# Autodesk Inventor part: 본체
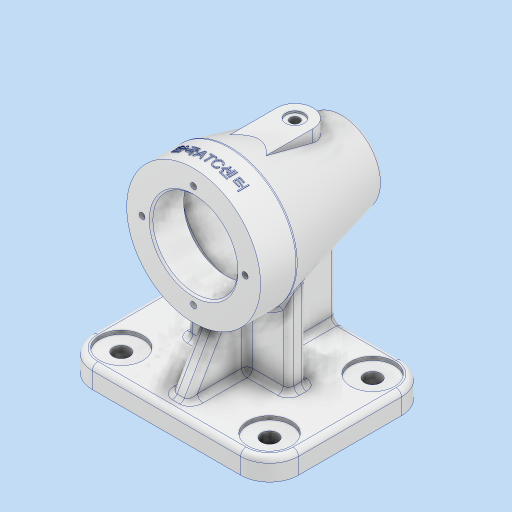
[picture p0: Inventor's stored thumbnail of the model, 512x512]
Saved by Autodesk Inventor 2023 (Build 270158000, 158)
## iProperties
Created: 2024-12
Part Number: 본체
Material: 알루미늄 6061
Document SubType Name: Modeling
Designer: asung
Density: 2.7 g/cm^3
Appearance: 알루미늄 - 평지
Mass: 746.172 g
Surface Area: 670.78 cm^2
Volume: 276.36 cm^3
Author: asung
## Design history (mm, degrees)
sketch "스케치1"
  geometry: L1 (-41, 44.5)-(41, 44.5); L2 (57, 28.5)-(57, -28.5); L3 (41, -44.5)-(-41, -44.5); L4 (-57, -28.5)-(-57, 28.5); L5 (-57, 44.5)-(57, -44.5); L6 (57, 44.5)-(-57, -44.5); C1 r 4.5 at (41, -28.5); C2 r 4.5 at (-41, -28.5); C3 r 4.5 at (-41, 28.5); C4 r 4.5 at (41, 28.5); A1 r 16 centre (41, -28.5) between (41, -44.5) and (57, -28.5); A2 r 16 centre (-41, -28.5) between (-57, -28.5) and (-41, -44.5); A3 r 16 centre (41, 28.5) between (57, 28.5) and (41, 44.5); A4 r 16 centre (-41, 28.5) between (-41, 44.5) and (-57, 28.5); 2 further points
  constraints: 12 end point, 8 centre point, 8 point on circle, 8 point on line, 8 tangent, 4 coincident, 3 equal radius, 3 midpoint, 2 parallel, 1 horizontal, 1 perpendicular
  dimensions: "d0" = 114 distance of L5.end L6.end; "d1" = 89 distance from line of point (0, 44.5) L3; "d2" = 16 radius of A1; "d3" = 4.5 radius of C1; "d4" = 4.5 radius of C2; "d6" = 4.5 radius of C3; "d7" = 4.5 radius of C4
extrude "돌출1" new body sketch "스케치1" distance "d8" = 12; taper "d9" = 0 deg
sketch "스케치2"
  geometry: A1 r 16 centre (-41, 28.5) between (-41, 44.5) and (-57, 28.5) reference; A2 r 16 centre (41, 28.5) between (57, 28.5) and (41, 44.5) reference; A3 r 16 centre (-41, -28.5) between (-57, -28.5) and (-41, -44.5) reference; A4 r 16 centre (41, -28.5) between (41, -44.5) and (57, -28.5) reference; 5 further points
  constraints: 4 coincident
hole "구멍1" sketch "스케치2" at (-41, 28.5), (41, 28.5), (-41, -28.5), (41, -28.5) diameter "d10" = 9; stored, may be unused: countersink angle "d14" = 90 deg, drill point angle "d16" = 0 deg; dims "d11" = 6, "d12" = 24, "d13" = 2, "d15" = 12
sketch "스케치3"
  geometry: L1 (12, -44.5)-(0, -44.5) reference; L2 (0, -44.5)-(0, 44.5) reference; L3 (0, 44.5)-(12, 44.5) reference; L4 (12, 44.5)-(12, -44.5) reference; L5 (82, -85.109)-(82, 114.888); L6 (119, 29.5)-(119, 9.5); L7 (119, 9.5)-(103, -54.5); L8 (103, -54.5)-(82, -54.5); L9 (82, -46.5)-(94.5, -46.5); L10 (97.5, -43.5)-(97.5, -43.5); L11 (97.5, -43.5)-(99.5, -43.5); L12 (103.664, -31.228)-(112.793, 5.287); L13 (107.942, 11.5)-(105.5, 11.5); L14 (105.5, 11.5)-(105.5, 29.5); L15 (105.5, 29.5)-(119, 29.5); L16 (99.5, -43.5)-(99.5, -33.5); L17 (99.5, -33.5)-(100.754, -33.5); A1 r 5 centre (107.942, 6.5) between (112.793, 5.287) and (107.942, 11.5); A2 r 3 centre (94.5, -43.5) between (94.5, -46.5) and (97.5, -43.5); A3 r 3 centre (100.754, -30.5) between (100.754, -33.5) and (103.664, -31.228); 4 further points
  constraints: 26 end point, 6 point on circle, 6 tangent, 4 vertical, 3 centre point, 3 perpendicular, 3 point on line, 2 horizontal, 2 parallel
  dimensions: "d17" = 82 distance between parallel lines of L5 L2; "d18" = 84 vertical distance of L6.start L8.end; "d19" = 15 vertical distance of L3.end L6.start; "d22" = 74 diameter of L6 L5; "d23" = 20 distance of L6.start L6.end; "d25" = 42 diameter of L7.end L5; "d26" = 18 distance of L13.end L14.end; "d27" = 5 distance between parallel lines of L7 L12; "d28" = 47 diameter of L14 L5; "d29" = 5 radius of A1; "d32" = 45 vertical distance of L13.end point (103.096, -33.5); "d33" = 3 distance between parallel lines of L11 L9; "d34" = 35 diameter of L16 L5; "d35" = 31 diameter of L10 L5; "d36" = 3 radius of A2; "d37" = 10 distance of L11.end L16.end; "d38" = 13 distance from line of L9 point (103.096, -33.5); "d39" = 3 radius of A3
revolve "회전1" sketch "스케치3" stored, may be unused: angle "d40" = 90 deg
node "작업 평면1"
sketch "스케치4"
  geometry: L1 (10, -26.5)-(-10, -26.5); L2 (-10, -26.5)-(-10, -0.572); L3 (10, -0.572)-(10, -26.5); L4 (10, -26.5)-(-10, 2.036); L5 (-10, -26.5)-(10, 2.036); L6 (37, 29.5)-(-37, 29.5) reference; L7 (-16.733, 9.5)-(-16.733, 29.5) reference; L8 (-16.733, 29.5)-(16.733, 29.5) reference; L9 (16.733, 29.5)-(16.733, 9.5) reference; L10 (-16.733, 9.5)-(-16.733, 29.5) reference; L11 (-16.733, 29.5)-(16.733, 29.5) reference; L12 (16.733, 29.5)-(16.733, 9.5) reference; C1 r 10 at (0, -26.5); 6 further points
  constraints: 10 end point, 3 midpoint, 1 centre point, 1 horizontal, 1 parallel, 1 perpendicular, 1 tangent, 4 other
  dimensions: "d42" = 56 distance from line of L6 C1.centre; "d43" = 20 distance between parallel lines of L2 L3; "d44" = 10 distance from line of L2 point (0, 0)
extrude "돌출2" join sketch "스케치4" stored distance "d45" = 10; taper "d46" = 0 deg
chamfer "모따기1" distance "d47" = 1; stored, may be unused: second distance "d48" = 2, angle "d49" = 45 deg
fillet "모깎기1" dims "d50" = 0.3
sketch "스케치5"
  geometry: A1 r 10 centre (0, 26.5) between (10, 26.5) and (-10, 26.5) reference; 2 further points
  constraints: 1 coincident
hole "구멍2" sketch "스케치5" at (0, 26.5) diameter "d51" = 5.1881; stored, may be unused: countersink angle "d55" = 90 deg, drill point angle "d57" = 0 deg; dims "d52" = 12, "d53" = 10, "d54" = 1, "d56" = 16
sketch "스케치6"
  geometry: L1 (41, 44.5)-(-41, 44.5) reference; L2 (-5, -5)-(5, -5); L3 (5, -5)-(5, 44.5); L4 (5, 44.5)-(-5, 44.5); L5 (-5, 44.5)-(-5, -5); L6 (-5, -5)-(5, 44.5); L7 (5, -5)-(-5, 44.5); L8 (-28, 5)-(28, 5); L9 (28, 5)-(28, -5); L10 (28, -5)-(-28, -5); L11 (-28, -5)-(-28, 5); L12 (-28, 5)-(28, -5); L13 (28, 5)-(-28, -5); 7 further points
  constraints: 24 end point, 5 midpoint, 4 parallel, 2 horizontal, 2 perpendicular, 2 point on line
  dimensions: "d59" = 56 distance of L8.start L8.end; "d60" = 5 distance of point (-5, 19.75) point (0, 19.75); "d61" = 0 horizontal distance of point (0, 0) point (0, 19.75); "d62" = 10 distance between parallel lines of L10 L8
extrude "돌출3" join sketch "스케치6" stored distance "d63" = 10; taper "d64" = 0 deg
sketch "스케치7"
  geometry: L1 (12, 37.5)-(45, 18.447); L2 (57.5, 29.5)-(58.5, 28.5) reference; L3 (58.5, 28.5)-(58.5, 11.5) reference; L4 (58.5, 11.5)-(56.058, 11.5) reference; L5 (51.207, 5.287)-(60.336, -31.228) reference; L6 (63.246, -33.5)-(63.5, -33.5) reference; L7 (63.5, -33.5)-(64.5, -34.5) reference; L8 (64.5, -34.5)-(64.5, -43.2) reference; L9 (64.8, -43.5)-(66.5, -43.5) reference; L10 (69.5, -46.5)-(94.5, -46.5) reference; L11 (97.5, -43.5)-(99.2, -43.5) reference; L12 (99.5, -43.2)-(99.5, -34.5) reference; L13 (99.5, -34.5)-(100.5, -33.5) reference; L14 (100.5, -33.5)-(100.754, -33.5) reference; L15 (103.664, -31.228)-(104.198, -29.094) reference; L16 (114, -23.906)-(105.495, -23.906) reference; L17 (114, -21.5)-(114, -23.906) reference; L18 (115, -21.5)-(114, -21.5) reference; L19 (115, -31.5)-(115, -36.5) reference; L20 (115, -36.5)-(107.5, -36.5) reference; L21 (107.5, -36.5)-(103, -54.5) reference; L22 (61, -54.5)-(58.5, -44.5) reference; L23 (58.5, -44.5)-(0, -44.5) reference; L24 (0, -44.5)-(0, 44.5) reference; L25 (0, 44.5)-(12, 44.5) reference; L26 (12, 44.5)-(12, 5) reference; L27 (12, 5)-(46.125, 5) reference; L28 (46.125, 5)-(45, 9.5) reference; L29 (45, 9.5)-(45, 29.5) reference; L30 (45, 29.5)-(57.5, 29.5) reference; L31 (105.5, 28.5)-(106.5, 29.5) reference; L32 (106.5, 29.5)-(119, 29.5) reference; L33 (119, 29.5)-(119, 9.5) reference; L34 (119, 9.5)-(115, -6.5) reference; L35 (115, -6.5)-(115, -21.5) reference; L36 (114, -31.5)-(115, -31.5) reference; L37 (114, -29.094)-(114, -31.5) reference; L38 (104.198, -29.094)-(114, -29.094) reference; L39 (105.495, -23.906)-(112.793, 5.287) reference; L40 (107.942, 11.5)-(105.5, 11.5) reference; L41 (105.5, 11.5)-(105.5, 28.5) reference; L42 (103, -54.5)-(61, -54.5) reference; A1 r 5 centre (56.058, 6.5) between (56.058, 11.5) and (51.207, 5.287) reference; A2 r 3 centre (63.246, -30.5) between (60.336, -31.228) and (63.246, -33.5) reference; A3 r 0.3 centre (64.8, -43.2) between (64.5, -43.2) and (64.8, -43.5) reference; A4 r 3 centre (69.5, -43.5) between (66.5, -43.5) and (69.5, -46.5) reference; A5 r 3 centre (94.5, -43.5) between (94.5, -46.5) and (97.5, -43.5) reference; A6 r 0.3 centre (99.2, -43.2) between (99.2, -43.5) and (99.5, -43.2) reference; A7 r 3 centre (100.754, -30.5) between (100.754, -33.5) and (103.664, -31.228) reference; A8 r 5 centre (107.942, 6.5) between (112.793, 5.287) and (107.942, 11.5) reference; 1 further point
  constraints: 2 end point, 2 point on line
  dimensions: "d65" = 7 distance from line of L25 L1.start; "d66" = 60 deg angle of L26 L1
feature "리브1" sketch "스케치7" dims "d67" = 1, "d68" = 10, "d69" = 0, "d70" = 0, "d71" = 1, "d72" = 1
fillet "모깎기3" dims "d73" = 3
fillet "모깎기4" dims "d74" = 3
fillet "모깎기5" dims "d75" = 3
fillet "모깎기6" dims "d76" = 3
node "작업 평면3"
sketch "스케치8"
  geometry: L1 (37, 10)-(-37, 10) reference; L2 (41, 25)-(-41, 25) reference; L3 (21, -74)-(-21, -74) reference; L4 (37, -10)-(-37, -10) reference; 4 further points
  constraints: 1 vertical alignment, 1 other
  dimensions: "d77" = 9 distance from line of L1 point (0, 1); "d79" = 84 distance between parallel lines of L1 L3 (derived); "d80" = 20 distance between parallel lines of L1 L4 (derived); "d81" = 99 distance between parallel lines of L2 L3 (derived)
feature "엠보싱1" sketch "스케치8" dims "d0" = 114, "d1" = 89, "d2" = 16, "d3" = 4.5, "d4" = 4.5, "d6" = 4.5, "d7" = 4.5, "d82" = 0.5, "d83" = 0
fillet "모깎기7" dims "d84" = 3
sketch "스케치9" dims "d86" = 57
  geometry: C1 r 37 at (0, 0) reference; C2 r 24.5 at (0, 0) reference; 6 further points
  constraints: 2 vertical alignment, 1 coincident, 7 other
  dimensions: "d89" = 360 deg dimension on C1.centre point (0, 28.5) (derived)
hole "구멍3" sketch "스케치9" at (0, 28.5), (-28.5, 0), (0, -28.5), (28.5, 0) diameter "d91" = 3.242; stored, may be unused: countersink angle "d95" = 90 deg, drill point angle "d97" = 118 deg; dims "d92" = 8, "d93" = 10, "d94" = 1, "d96" = 10
feature "΁耀΃耀΅耀·耀Ή耀΋耀΍耀Ώ耀" dims "d0" = 114, "d1" = 89, "d2" = 16, "d3" = 4.5, "d4" = 4.5, "d6" = 4.5, "d7" = 4.5, "d8" = 12, "d9" = 0, "d10" = 9, "d11" = 6, "d12" = 24, "d13" = 2, "d14" = 90 deg, "d15" = 12, "d16" = 0, "d17" = 82, "d18" = 84, "d19" = 15, "d22" = 74, "d23" = 20, "d25" = 42, "d26" = 18, "d27" = 5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
node "솔리드1"
node "절단 모서리 투영1"
node "절단 모서리 투영2"
node "절단 모서리 투영3"
node "절단 모서리 투영4"
feature "A9D066F2-1C7D-4E18-AEED-F7BC21143FA4" dims "d10" = 9, "d11" = 6, "d12" = 24, "d13" = 2, "d14" = 90 deg, "d15" = 12, "d16" = 0
